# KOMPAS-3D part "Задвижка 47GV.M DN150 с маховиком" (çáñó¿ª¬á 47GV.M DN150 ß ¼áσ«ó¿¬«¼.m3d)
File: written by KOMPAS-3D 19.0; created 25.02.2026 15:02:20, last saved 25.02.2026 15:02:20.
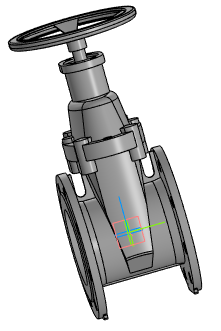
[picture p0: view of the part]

Document properties: Автор: Энергия; Полное имя файла: 47GV.M DN125\Задвижка 47GV.M DN125 с маховиком.a3d

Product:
- Part/product: Задвижка 47GV.M DN150 с маховиком
    Масса: 51.6377
    source file: 47GV.M DN150\DR.47GVM.125.16.00.00 - Задвижка с обрезиненным клином DN125.spw
  - Component: Задвижка с обрезиненным клином DN125. Сборочный чертеж  | designation DR.47GVM.125.16.00.00СБ  | pos. 0  | Масса: 25.3494; Раздел спецификации: Документация; Форматы листов документа: 2xA3; source file: 47GV.M DN150\DR.47GVM.125.16.00.000 СБ - Задвижка с обрезиненным клином DN125.cdw

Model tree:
1. Операция без истории:1

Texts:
  Точка начала. Х
  Точка начала. Y
  Точка начала. Z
